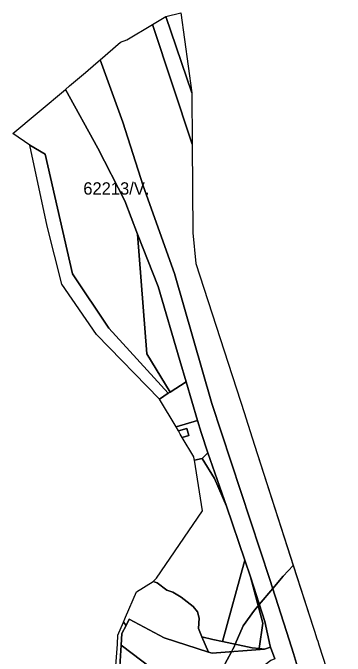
# Model space of a CAD drawing. Extents: x -502026 to -497664, y -1143484 to -1138019.
# Drawn here: x -498059.9 to -497844.7, y -1138435.9 to -1138019.3 of the extents above; entities that cross this region are included whole.
import ezdxf

# ---------------------------------------------------------------- set-up
doc = ezdxf.new("R2010")
doc.units = 0
for name, color, linetype in [('25', 7, 'Continuous'), ('37', 7, 'Continuous'), ('49', 7, 'Continuous'), ('55', 7, 'Continuous'), ('62', 7, 'Continuous'), ('7', 7, 'Continuous')]:
    doc.layers.add(name, color=color, linetype=linetype)

msp = doc.modelspace()

# ---------------------------------------------------------------- linework, layer by layer
at = {"layer": '25'}
msp.add_lwpolyline([(-497906.02, -1138384.62), (-497897.92, -1138414.59), (-497900.3, -1138430.99), (-497904.86, -1138430.54), (-497924.09, -1138426.46), (-497909.68, -1138373.88)], close=True, dxfattribs=at)
at = {"layer": '37'}
for points in [[(-497940.22, -1138283.23), (-497954.15, -1138287.49), (-497964.98, -1138269.51), (-497959.33, -1138265.7), (-497958.07, -1138264.91), (-497947.61, -1138258.35)], [(-497921.61, -1138338.83), (-497909.68, -1138373.88), (-497924.09, -1138426.46), (-497930.39, -1138425.28), (-497937.46, -1138423.55), (-497939.72, -1138418.12), (-497939.27, -1138411.37), (-497940.4, -1138407.19), (-497943.06, -1138403.76), (-497950.97, -1138397.77), (-497956.4, -1138394.56), (-497960.17, -1138393.13), (-497966.5, -1138388.58), (-497969.1, -1138387.64), (-497966.85, -1138385.45), (-497937.15, -1138341.75), (-497942.29, -1138309.1), (-497937.33, -1138308.05), (-497929.26, -1138320.87)]]:
    msp.add_lwpolyline(points, close=True, dxfattribs=at)
at = {"layer": '49'}
msp.add_lwpolyline([(-497874.17, -1138447.19), (-497878.23, -1138434.33), (-497881.04, -1138425.41), (-497893.39, -1138386.29), (-497930.98, -1138272.26), (-497955.25, -1138188.18), (-497975.46, -1138131.35), (-497988.77, -1138090.05), (-498003.46, -1138049.73), (-497990.17, -1138038.33), (-497986.07, -1138036.87), (-497969.54, -1138026.9), (-497943.81, -1138104.29), (-497943.4, -1138161.69), (-497941.29, -1138181.62), (-497909.97, -1138278.82), (-497909.05, -1138281.67), (-497903.34, -1138299.38), (-497865.39, -1138417.14), (-497864.94, -1138418.54), (-497864.52, -1138419.83), (-497862.95, -1138424.72), (-497862.47, -1138426.21), (-497861.66, -1138428.73), (-497844.68, -1138481.4)], dxfattribs=at)
at = {"layer": '55'}
for points in [[(-497944.04, -1138071.14), (-497943.81, -1138104.29), (-497969.54, -1138026.9), (-497960.73, -1138021.59)], [(-497944.04, -1138071.14), (-497960.73, -1138021.59), (-497951.09, -1138019.31)], [(-497933.63, -1138304.29), (-497937.33, -1138308.05), (-497942.29, -1138309.1), (-497942.4, -1138308.38), (-497942.64, -1138306.87), (-497950.24, -1138294.26), (-497945.92, -1138292.95), (-497947.3, -1138288.42), (-497952.69, -1138290.06), (-497954.15, -1138287.49), (-497940.22, -1138283.23), (-497937.91, -1138291.03)], [(-497950.24, -1138294.26), (-497951.51, -1138292.15), (-497952.69, -1138290.06), (-497947.3, -1138288.42), (-497945.92, -1138292.95)], [(-497921.61, -1138338.83), (-497929.26, -1138320.87), (-497937.33, -1138308.05), (-497933.63, -1138304.29)], [(-497892.94, -1138430.17), (-497896.85, -1138431.33), (-497900.3, -1138430.99), (-497897.92, -1138414.59), (-497906.02, -1138384.62), (-497896.78, -1138413.6), (-497893.17, -1138429.5)], [(-497939.27, -1138411.37), (-497939.72, -1138418.12), (-497937.46, -1138423.55), (-497933.11, -1138433.34), (-497961.84, -1138424.14), (-497984.51, -1138412.05), (-497986.62, -1138416.11), (-497988.33, -1138414.02), (-497986.91, -1138410.68), (-497979.9, -1138394.24), (-497969.1, -1138387.64), (-497966.5, -1138388.58), (-497960.17, -1138393.13), (-497956.4, -1138394.56), (-497950.97, -1138397.77), (-497943.06, -1138403.76), (-497940.4, -1138407.19)], [(-497986.62, -1138416.11), (-497989.33, -1138421.31), (-497989.8, -1138428.9), (-497992.16, -1138466.85), (-497993.08, -1138477.56), (-497987.41, -1138489.31), (-497993.46, -1138523.87), (-497989.25, -1138545.57), (-497990.06, -1138561.14), (-497992.33, -1138562.45), (-497992.79, -1138546.37), (-497996.81, -1138523.76), (-497990.82, -1138490.42), (-497995.99, -1138478.64), (-497992.07, -1138428.18), (-497991.82, -1138422.28), (-497988.33, -1138414.02)], [(-497933.11, -1138433.34), (-497930.71, -1138434.11), (-497896.85, -1138431.33), (-497892.94, -1138430.17), (-497890.32, -1138437.79), (-497892.86, -1138438.79), (-497896.46, -1138441.53), (-497910.13, -1138451.93), (-497917.44, -1138451.92), (-497939.13, -1138451.6), (-497970.13, -1138443.81), (-497989.8, -1138428.9), (-497989.33, -1138421.31), (-497986.62, -1138416.11), (-497984.51, -1138412.05), (-497961.84, -1138424.14)], [(-497924.09, -1138426.46), (-497904.86, -1138430.54), (-497900.3, -1138430.99), (-497896.85, -1138431.33), (-497930.71, -1138434.11), (-497933.11, -1138433.34), (-497937.46, -1138423.55), (-497930.39, -1138425.28)]]:
    msp.add_lwpolyline(points, close=True, dxfattribs=at)
msp.add_lwpolyline([(-497890.32, -1138437.79), (-497892.94, -1138430.17), (-497893.17, -1138429.5), (-497896.78, -1138413.6), (-497906.02, -1138384.62), (-497909.68, -1138373.88), (-497921.61, -1138338.83), (-497933.63, -1138304.29), (-497937.91, -1138291.03), (-497940.22, -1138283.23), (-497947.61, -1138258.35), (-497951.68, -1138244.57), (-497965.73, -1138196.49), (-497979.08, -1138162.54), (-497987.36, -1138141.13), (-498004.81, -1138106.91), (-498025.92, -1138068.99), (-498023.2, -1138066.66), (-498012.96, -1138057.88), (-498006.14, -1138052.03), (-498003.46, -1138049.73), (-497988.77, -1138090.05), (-497975.46, -1138131.35), (-497955.25, -1138188.18), (-497930.98, -1138272.26), (-497893.39, -1138386.29), (-497881.04, -1138425.41), (-497878.23, -1138434.33), (-497874.17, -1138447.19)], dxfattribs=at)
at = {"layer": '62'}
for points in [[(-497995.99, -1138478.64), (-497992.07, -1138428.18), (-497991.82, -1138422.28), (-497988.33, -1138414.02), (-497986.91, -1138410.68), (-497979.9, -1138394.24), (-497969.1, -1138387.64), (-497966.85, -1138385.45), (-497937.15, -1138341.75), (-497942.29, -1138309.1), (-497942.4, -1138308.38), (-497942.64, -1138306.87), (-497950.24, -1138294.26), (-497951.51, -1138292.15), (-497952.69, -1138290.06), (-497954.15, -1138287.49), (-497964.98, -1138269.51), (-498005.65, -1138227.72), (-498028.22, -1138195.03), (-498037.7, -1138157.43), (-498048.94, -1138104.92), (-498059.92, -1138097.54), (-498025.92, -1138068.99), (-498023.2, -1138066.66), (-498012.96, -1138057.88), (-498006.14, -1138052.03), (-498003.46, -1138049.73), (-497990.17, -1138038.33), (-497986.07, -1138036.87), (-497969.54, -1138026.9), (-497960.73, -1138021.59), (-497951.09, -1138019.31), (-497944.04, -1138071.14), (-497943.81, -1138104.29), (-497943.4, -1138161.69), (-497941.29, -1138181.62), (-497909.97, -1138278.82), (-497909.05, -1138281.67), (-497903.34, -1138299.38), (-497878.27, -1138377.17), (-497884.78, -1138384.12), (-497891.55, -1138392.13), (-497900.31, -1138402.51), (-497900.97, -1138403.29), (-497903.47, -1138406.25), (-497910.69, -1138416.37), (-497915.87, -1138428.2), (-497916.66, -1138430), (-497917.47, -1138431.54), (-497918.29, -1138433.09), (-497923.87, -1138443.62)], [(-497923.87, -1138443.62), (-497918.29, -1138433.09), (-497917.47, -1138431.54), (-497916.66, -1138430), (-497915.87, -1138428.2), (-497910.69, -1138416.37), (-497903.47, -1138406.25), (-497900.97, -1138403.29), (-497900.31, -1138402.51), (-497891.55, -1138392.13), (-497884.78, -1138384.12), (-497878.27, -1138377.17), (-497865.39, -1138417.14), (-497864.94, -1138418.54), (-497864.52, -1138419.83), (-497862.95, -1138424.72), (-497862.47, -1138426.21), (-497861.66, -1138428.73), (-497844.68, -1138481.4)]]:
    msp.add_lwpolyline(points, dxfattribs=at)
at = {"layer": '7'}
for points in [[(-497979.08, -1138162.54), (-497973.13, -1138240.19), (-497958.07, -1138264.91), (-497959.33, -1138265.7), (-497997.65, -1138223.59), (-498021.34, -1138188.24), (-498039.01, -1138110.81), (-498048.94, -1138104.92), (-498059.92, -1138097.54), (-498025.92, -1138068.99), (-498004.81, -1138106.91), (-497987.36, -1138141.13)], [(-497959.33, -1138265.7), (-497964.98, -1138269.51), (-498005.65, -1138227.72), (-498028.22, -1138195.03), (-498037.7, -1138157.43), (-498048.94, -1138104.92), (-498039.01, -1138110.81), (-498021.34, -1138188.24), (-497997.65, -1138223.59)], [(-497947.61, -1138258.35), (-497958.07, -1138264.91), (-497973.13, -1138240.19), (-497979.08, -1138162.54), (-497965.73, -1138196.49), (-497951.68, -1138244.57)], [(-497917.44, -1138451.92), (-497918.84, -1138485.4), (-497927.08, -1138499.92), (-497927.5, -1138500.66), (-497983.15, -1138453.32), (-497992.16, -1138466.85), (-497989.8, -1138428.9), (-497970.13, -1138443.81), (-497939.13, -1138451.6)]]:
    msp.add_lwpolyline(points, close=True, dxfattribs=at)

# ---------------------------------------------------------------- texts
at = {"layer": '62'}
msp.add_text('62213/V.', height=8, dxfattribs=at).set_placement((-498014.29, -1138137.04))

doc.saveas('drawing.dxf')
